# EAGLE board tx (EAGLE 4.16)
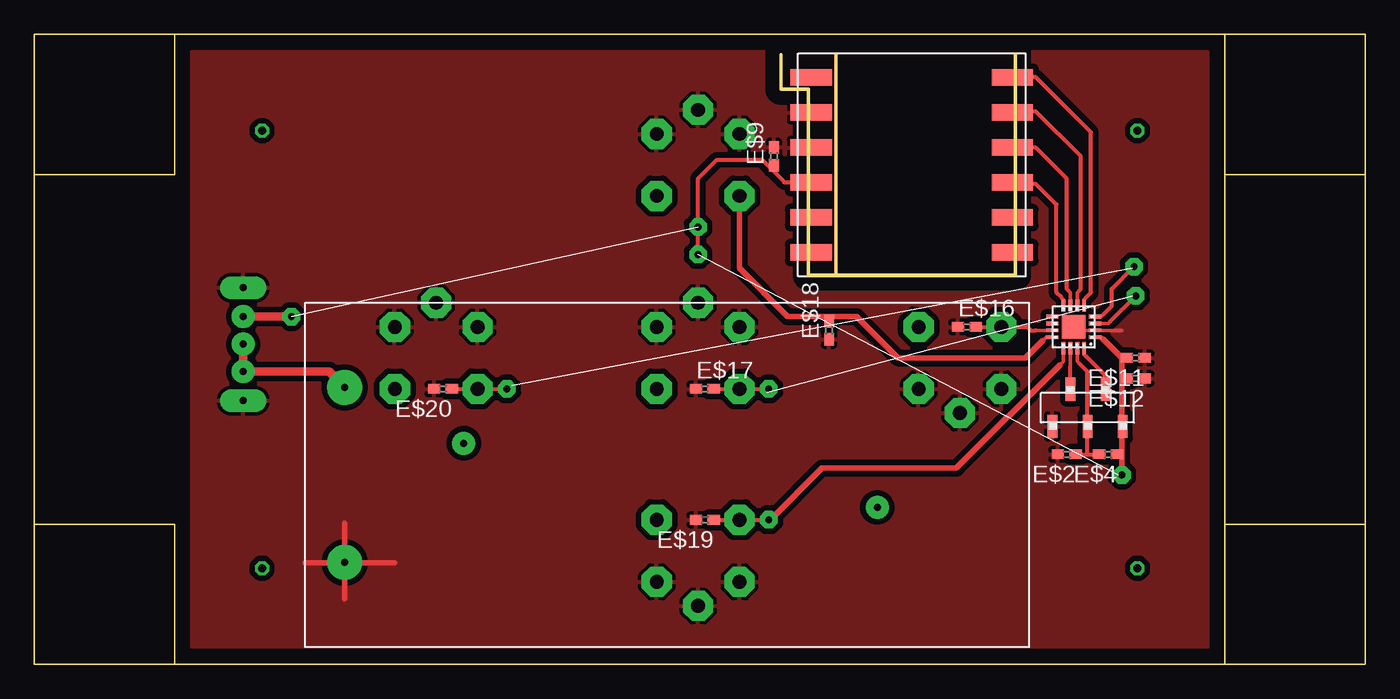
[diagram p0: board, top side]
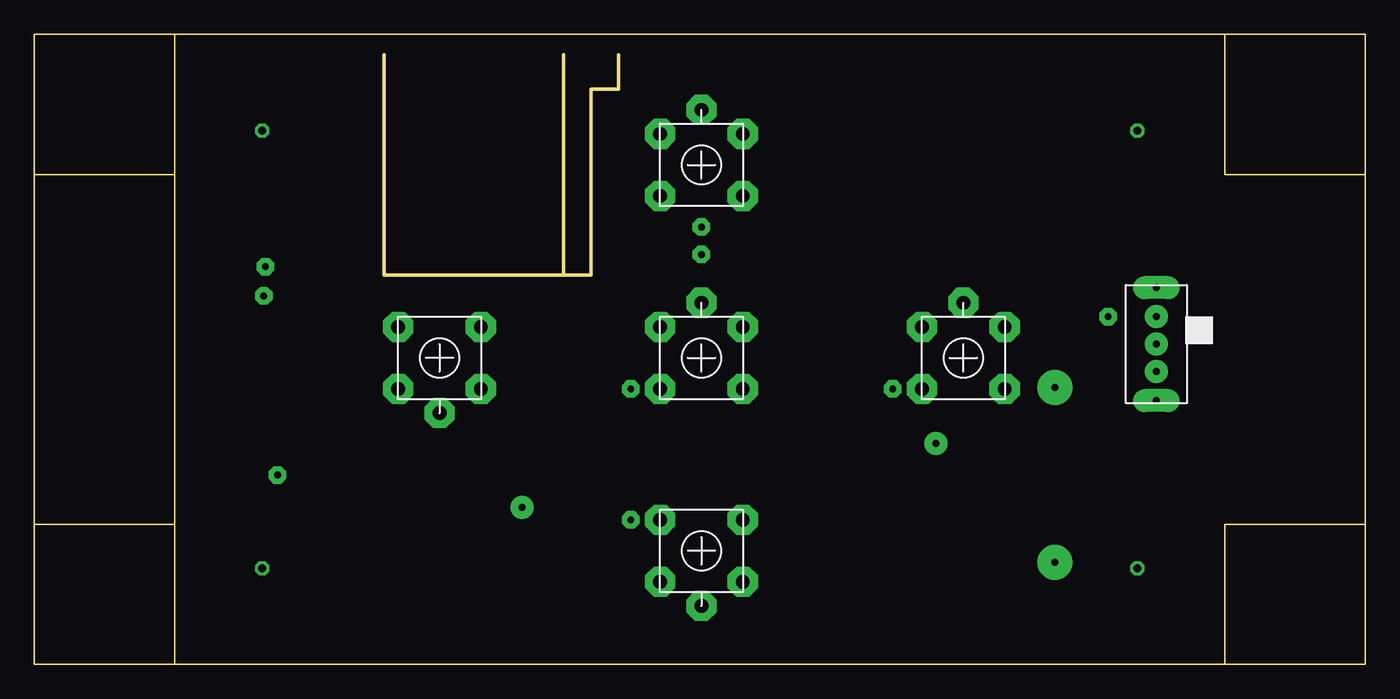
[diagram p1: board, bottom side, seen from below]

Size 96.52 x 45.72 mm. Coordinates in mm from the lower left corner, seen from the top.
Outline: 0,10.16 0,0 10.16,0
Outline: 0,10.16 0,35.56
Outline: 0,35.56 0,45.72 10.16,45.72
Outline: 86.36,45.72 86.36,35.56
Outline: 86.36,35.56 86.36,10.16
Outline: 86.36,10.16 86.36,0
Outline: 86.36,0 10.16,0
Outline: 10.16,45.72 86.36,45.72
Outline: 86.36,45.72 96.52,45.72 96.52,35.56
Outline: 96.52,35.56 96.52,10.16
Outline: 96.52,10.16 96.52,0 86.36,0
Outline: 0,10.16 10.16,10.16 10.16,0
Outline: 0,35.56 10.16,35.56 10.16,45.72
Outline: 86.36,35.56 96.52,35.56
Outline: 86.36,10.16 96.52,10.16
Outline: 54.14,44.25 54.14,41.75 56.14,41.75 56.14,28.25 71.14,28.25 71.14,44.25
Outline: 58.14,28.25 58.14,44.25
Copper layers (1*16): Top 0.035mm / dielectric 1.5mm / Bottom 0.035mm
Design rules "default": minimum track width 10mil, minimum drill 24mil, track to track 8mil, track to pad 8mil, pad to pad 8mil, via to via 8mil, smd to smd 8mil, copper to edge 40mil, drill to drill 8mil, minimum pad ring 10mil, minimum via ring 8mil, stop-mask expansion 4mil, vias tented up to drill 0mil, thermal gap 10mil

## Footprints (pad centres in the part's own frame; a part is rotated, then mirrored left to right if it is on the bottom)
QFN16 = smd 0.9 x 0.28: 1 -1.3,0.5; 2 -1.3,0; 3 -1.3,-0.5; 4 -1.3,-1; 9 1.8,-1; 10 1.8,-0.5; 11 1.8,0; 12 1.8,0.5 | smd 0.28 x 0.9: 5 -0.5,-1.8; 6 0,-1.8; 7 0.5,-1.8; 8 1,-1.8; 13 1,1.3; 14 0.5,1.3; 15 0,1.3; 16 -0.5,1.3 | smd 1.7 x 1.7: EP 0.25,-0.25
C0402 = smd 0.9 x 0.7: 1 -0.65,0; 2 0.65,0
HEADER5S = smd 0.7 x 1.7: P$1 0,1.35; P$2 2.55,1.35; P$3 -2.55,1.35; P$4 -1.3,-1.35; P$5 1.25,-1.35
SS-12D07 = drill 1 pad 2.184 octagon: P$1 -2.25,3; P$2 2.25,3; P$3 2.25,-3; P$4 -2.25,-3; P$5 4,0
SLIDER4 = drill 0.5 pad 1.676 round: P$1 0,2; P$2 0,0; P$3 0,-2 | drill 0.5 pad 1.676 long: P$4 0,4.1; P$5 0,-4.1
ZETA-RF = smd 3 x 1.2: 1 -7.303,6.35; 2 -7.303,3.81; 3 -7.303,1.27; 4 -7.303,-1.27; 5 -7.303,-3.81; 6 -7.303,-6.35; 7 7.303,-6.35; 8 7.303,-3.81; 9 7.303,-1.27; 10 7.303,1.27; 11 7.303,3.81; 12 7.303,6.35
2XAAA_B = drill 0.5 pad 1.676 round: P$1 -15,2.35; P$2 15,-2.3 | drill 0.5 pad 2.54 round: P$3 23.65,6.35; P$4 23.65,-6.35

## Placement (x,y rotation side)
E$1  [QFN16]  75.64,24.25 180 top
E$2  [C0402]  74.89,15.25 180 top
E$3  [HEADER5S]  76.39,18.62 180 top
E$4  [C0402]  77.89,15.25 180 top
E$5  [SS-12D07]  67.14,22.25 270 bottom
E$6  [SS-12D07]  29.14,22.25 90 bottom
E$7  [SS-12D07]  48.14,36.25 90 bottom
E$8  [SS-12D07]  48.14,8.25 270 bottom
E$9  [C0402]  53.64,36.88 90 top
E$10  [SLIDER4]  15.14,23.25 180 bottom
E$11  [C0402]  79.89,22.25 180 top
E$12  [C0402]  79.89,20.75 180 top
E$13  [ZETA-RF]  63.64,36.25 0 top
E$14  [SS-12D07]  48.14,22.25 90 bottom
E$15  [2XAAA_B]  46.14,13.75 180 top
E$16  [C0402]  67.64,24.5 0 top
E$17  [C0402]  48.64,20 0 top
E$18  [C0402]  57.64,24.25 90 top
E$19  [C0402]  48.64,10.5 180 top
E$20  [C0402]  29.64,20 180 top

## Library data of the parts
E$1 = freescale
E$2 E$4 E$9 E$11 E$12 E$16-E$20 = ref-packages
E$3 E$10 = sb
E$5-E$8 E$14 = switch-tactile
E$13 = silabs
E$15 = battery

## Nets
GND: E$2.2 E$3.P$2 E$5.P$2 E$5.P$3 E$5.P$5 E$6.P$2 E$6.P$3 E$6.P$5 E$7.P$2 E$7.P$3 E$7.P$5 E$8.P$2 E$8.P$3 E$8.P$5 E$9.2 E$10.P$4 E$10.P$5 E$11.1 E$12.1 E$13.2 E$13.3 E$14.P$2 E$14.P$3 E$14.P$5 E$16.1 E$17.1 E$18.1 E$19.2 E$20.2
S$43: E$10.P$1 E$10.P$2
S$45: E$10.P$3

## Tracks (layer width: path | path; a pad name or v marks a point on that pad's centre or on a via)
GND
  Top 0.254: 76.14,24.25 78.89,24.25
  Top 0.406: 19.64,7.38 26.14,7.38 | 22.52,4.75 22.52,10.25
  pour Top (isolate 0.406): 85.09,1.27 11.43,1.27 11.43,44.45 85.09,44.45
S$2  (via drill 0.6)
  other vias: 16.51,6.99
S$11
  Top 0.254: 75.77,21.88 75.64,22 75.64,22.75
  Top 0.305: 76.39,15.25 76.39,21.25 75.77,21.88
S$12
  Top 0.254: 76.27,22.38 76.14,22.5 76.14,22.75
  Top 0.305: 76.27,22.38 77.64,21 77.64,20.38
S$13
  Top 0.254: 75.14,21.62 75.14,22.75
  Top 0.305: 75.14,19.75 75.14,21.62
S$14
  Top 0.305: 75.89,15.25 77.39,15.25
S$15
  Top 0.406: 78.89,13.75 78.89,17.25
S$16
  Top 0.254: 77.52,23.62 77.39,23.75 76.89,23.75
  Top 0.406: 77.52,23.62 78.89,22.25 78.89,17.75
S$17
  Top 0.254: 72.64,24.25 73.64,24.25
  Top 0.305: 72.64,24.25 72.27,24.25 72.02,24.5 68.39,24.5
S$18
  Top 0.254: 76.14,26.25 76.14,26.5 76.27,26.62
  Top 0.305: 71.27,42.62 72.64,42.62 76.64,38.62 76.64,27 76.27,26.62
S$19
  Top 0.254: 75.64,26.25 75.64,27 75.77,27.12
  Top 0.305: 71.27,40.12 72.64,40.12 75.89,36.88 75.89,27.25 75.77,27.12
S$20
  Top 0.254: 75.14,26.25 75.14,27 75.02,27.12
  Top 0.305: 71.89,37.5 72.64,37.5 74.89,35.25 74.89,27.25 75.02,27.12
S$21
  Top 0.254: 74.52,26.62 74.64,26.5 74.64,26.25
  Top 0.305: 71.52,34.88 72.64,34.88 74.14,33.38 74.14,27 74.52,26.62
S$22
  Top 0.254: 71.64,29.75 72.14,29.75
S$25
  Top 0.254: 73.14,23.5 73.39,23.75 73.64,23.75
  Top 0.406: 73.14,23.5 71.89,22.25 62.64,22.25 59.64,25.25 54.64,25.25 51.14,28.75 51.14,33.75
S$26  (via drill 0.5 pad 1.27)
  other vias: 53.27,10.5
S$27  (via drill 0.5 pad 1.27)
  other vias: 79.77,28.88
S$28
  Top 0.305: 30.64,20 34.27,20
S$29  (via drill 0.6)
  other vias: 16.51,38.73
S$30
  Top 0.305: 49.14,10.5 53.27,10.5
S$31  (via drill 0.6)
  other vias: 80.01,38.73
S$32  (via drill 0.6)
  other vias: 80.01,6.99
S$33
  Top 0.254: 76.89,24.75 77.89,24.75 78.02,24.88
  Top 0.305: 78.02,24.88 79.89,26.75
S$34  (via drill 0.5 pad 1.27)
  other vias: 34.27,20
S$35  (via drill 0.5 pad 1.27)
  other vias: 79.89,26.75
S$36
  Top 0.254: 76.89,25.25 77.39,25.25 77.52,25.38
  Top 0.305: 77.52,25.38 78.14,26 78.14,27.25 79.77,28.88
S$38
  Top 0.254: 74.39,21.75 74.64,22 74.64,22.75
  Top 0.406: 53.39,10.5 57.14,14.25 66.89,14.25 74.39,21.75
S$39
  Top 0.305: 49.39,20 53.27,20
S$41
  Top 0.305: 55.64,35 54.39,35 52.77,36.62 49.52,36.62 48.14,35.25 48.14,31.75
S$42  (via drill 0.5 pad 1.27)
  other vias: 53.27,20
S$43
  Top 0.61: 22.64,20 21.39,21.25 E$10.P$1 E$10.P$2
S$44  (via drill 0.5 pad 1.27)
  other vias: 78.89,13.75
S$45  (via drill 0.5 pad 1.27)
  Top 0.61: E$10.P$3 v18.64,25.25
S$46  (via drill 0.5 pad 1.27)
  Top 0.305: v48.14,29.75 v48.14,31.75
